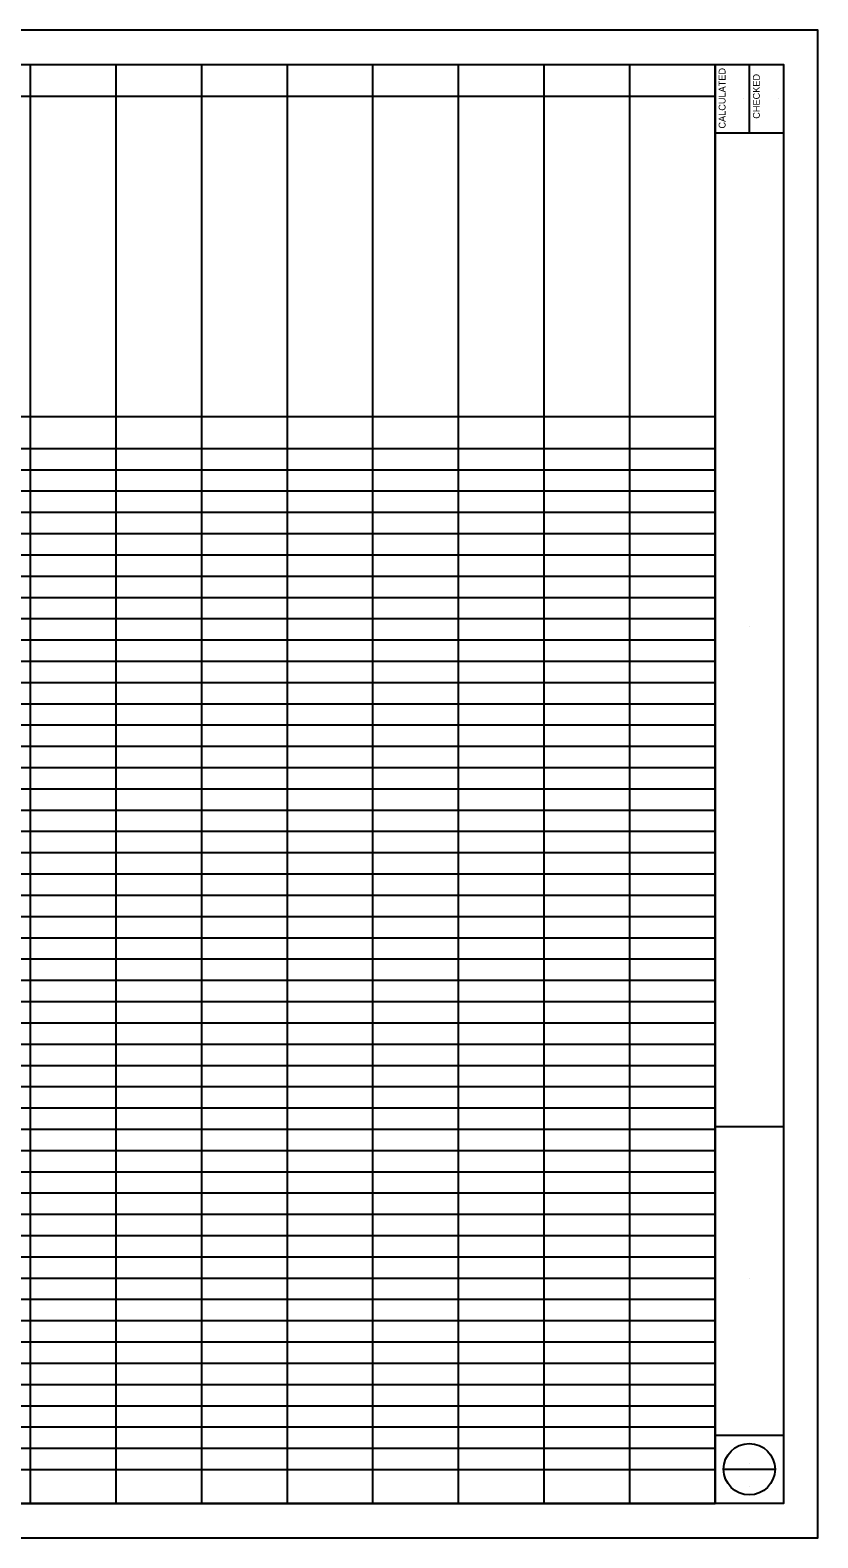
# Model space of a CAD drawing. Extents: x 10.3 to 44.3, y 3.4 to 25.4.
# Drawn here: x 32.81 to 44.31, y 3.4 to 25.4 of the extents above; entities that cross this region are included whole.
import ezdxf

# ---------------------------------------------------------------- set-up
doc = ezdxf.new("R2010")
doc.units = 0
for name, color, linetype in [('SH_Border', 7, 'Continuous'), ('SH_Cut_Line', 7, 'Continuous'), ('SH_Data', 7, 'Continuous'), ('SH_Text', 7, 'Continuous')]:
    doc.layers.add(name, color=color, linetype=linetype)

msp = doc.modelspace()

# ---------------------------------------------------------------- linework, layer by layer
at = {"layer": 'SH_Border'}
for p, q in [((42.806, 3.905), (42.806, 24.905)), ((43.306, 24.905), (43.306, 23.905)), ((42.806, 23.905), (43.806, 23.905)), ((42.806, 9.405), (43.806, 9.405)), ((42.806, 4.905), (43.806, 4.905))]:
    msp.add_line(p, q, dxfattribs=at)
msp.add_lwpolyline([(12.306, 24.905), (43.806, 24.905), (43.806, 3.905), (12.306, 3.905)], close=True, dxfattribs=at)
at = {"layer": 'SH_Cut_Line'}
msp.add_lwpolyline([(10.306, 3.405), (44.306, 3.405), (44.306, 25.405), (10.306, 25.405)], close=True, dxfattribs=at)
at = {"layer": 'SH_Data'}
for p, q in [((43.226, 24.408), (43.226, 24.408)), ((43.726, 24.408), (43.726, 24.408)), ((43.306, 16.696), (43.306, 16.696)), ((43.306, 7.196), (43.306, 7.196)), ((42.931, 4.405), (43.681, 4.405)), ((43.306, 4.49), (43.306, 4.49)), ((43.306, 4.15), (43.306, 4.15))]:
    msp.add_line(p, q, dxfattribs=at)
msp.add_circle((43.306, 4.405), 0.375, dxfattribs=at)
at = {"layer": 'SH_Text'}
for p, q in [((24.657, 24.905), (32.81, 24.905)), ((32.81, 24.905), (36.559, 24.905)), ((32.81, 24.905), (32.81, 19.767)), ((34.06, 24.905), (34.06, 19.767)), ((35.309, 24.905), (35.309, 19.767)), ((36.559, 24.905), (39.058, 24.905)), ((36.559, 24.905), (36.559, 19.767)), ((37.808, 24.905), (37.808, 19.767)), ((39.058, 24.905), (42.806, 24.905)), ((39.058, 24.905), (39.058, 19.767)), ((40.307, 24.905), (40.307, 19.767)), ((41.557, 24.905), (41.557, 19.767)), ((42.806, 24.905), (42.806, 19.767)), ((25.682, 24.439), (32.81, 24.439)), ((32.81, 24.439), (36.559, 24.439)), ((36.559, 24.439), (39.058, 24.439)), ((39.058, 24.439), (42.806, 24.439)), ((25.682, 19.767), (32.81, 19.767)), ((32.81, 19.767), (36.559, 19.767)), ((32.81, 19.767), (32.81, 11.851)), ((34.06, 19.767), (34.06, 11.851)), ((35.309, 19.767), (35.309, 11.851)), ((36.559, 19.767), (39.058, 19.767)), ((36.559, 19.767), (36.559, 11.851)), ((37.808, 19.767), (37.808, 11.851)), ((39.058, 19.767), (42.806, 19.767)), ((39.058, 19.767), (39.058, 11.851)), ((40.307, 19.767), (40.307, 11.851)), ((41.557, 19.767), (41.557, 11.851)), ((42.806, 19.767), (42.806, 11.851)), ((24.657, 19.301), (32.81, 19.301)), ((32.81, 19.301), (36.559, 19.301)), ((36.559, 19.301), (39.058, 19.301)), ((39.058, 19.301), (42.806, 19.301)), ((24.657, 18.991), (32.81, 18.991)), ((32.81, 18.991), (36.559, 18.991)), ((36.559, 18.991), (39.058, 18.991)), ((39.058, 18.991), (42.806, 18.991)), ((24.657, 18.681), (32.81, 18.681)), ((32.81, 18.681), (36.559, 18.681)), ((36.559, 18.681), (39.058, 18.681)), ((39.058, 18.681), (42.806, 18.681)), ((24.657, 18.37), (32.81, 18.37)), ((32.81, 18.37), (36.559, 18.37)), ((36.559, 18.37), (39.058, 18.37)), ((39.058, 18.37), (42.806, 18.37)), ((24.657, 18.06), (32.81, 18.06)), ((32.81, 18.06), (36.559, 18.06)), ((36.559, 18.06), (39.058, 18.06)), ((39.058, 18.06), (42.806, 18.06)), ((24.657, 17.749), (32.81, 17.749)), ((32.81, 17.749), (36.559, 17.749)), ((36.559, 17.749), (39.058, 17.749)), ((39.058, 17.749), (42.806, 17.749)), ((24.657, 17.439), (32.81, 17.439)), ((32.81, 17.439), (36.559, 17.439)), ((36.559, 17.439), (39.058, 17.439)), ((39.058, 17.439), (42.806, 17.439)), ((24.657, 17.128), (32.81, 17.128)), ((32.81, 17.128), (36.559, 17.128)), ((36.559, 17.128), (39.058, 17.128)), ((39.058, 17.128), (42.806, 17.128)), ((24.657, 16.818), (32.81, 16.818)), ((32.81, 16.818), (36.559, 16.818)), ((36.559, 16.818), (39.058, 16.818)), ((39.058, 16.818), (42.806, 16.818)), ((24.657, 16.508), (32.81, 16.508)), ((32.81, 16.508), (36.559, 16.508)), ((36.559, 16.508), (39.058, 16.508)), ((39.058, 16.508), (42.806, 16.508)), ((24.657, 16.197), (32.81, 16.197)), ((32.81, 16.197), (36.559, 16.197)), ((36.559, 16.197), (39.058, 16.197)), ((39.058, 16.197), (42.806, 16.197)), ((24.657, 15.887), (32.81, 15.887)), ((32.81, 15.887), (36.559, 15.887)), ((36.559, 15.887), (39.058, 15.887)), ((39.058, 15.887), (42.806, 15.887)), ((24.657, 15.576), (32.81, 15.576)), ((32.81, 15.576), (36.559, 15.576)), ((36.559, 15.576), (39.058, 15.576)), ((39.058, 15.576), (42.806, 15.576)), ((24.657, 15.266), (32.81, 15.266)), ((32.81, 15.266), (36.559, 15.266)), ((36.559, 15.266), (39.058, 15.266)), ((39.058, 15.266), (42.806, 15.266)), ((24.657, 14.956), (32.81, 14.956)), ((32.81, 14.956), (36.559, 14.956)), ((36.559, 14.956), (39.058, 14.956)), ((39.058, 14.956), (42.806, 14.956)), ((24.657, 14.645), (32.81, 14.645)), ((32.81, 14.645), (36.559, 14.645)), ((36.559, 14.645), (39.058, 14.645)), ((39.058, 14.645), (42.806, 14.645)), ((24.657, 14.335), (32.81, 14.335)), ((32.81, 14.335), (36.559, 14.335)), ((36.559, 14.335), (39.058, 14.335)), ((39.058, 14.335), (42.806, 14.335)), ((24.657, 14.024), (32.81, 14.024)), ((32.81, 14.024), (36.559, 14.024)), ((36.559, 14.024), (39.058, 14.024)), ((39.058, 14.024), (42.806, 14.024)), ((24.657, 13.714), (32.81, 13.714)), ((32.81, 13.714), (36.559, 13.714)), ((36.559, 13.714), (39.058, 13.714)), ((39.058, 13.714), (42.806, 13.714)), ((24.657, 13.403), (32.81, 13.403)), ((32.81, 13.403), (36.559, 13.403)), ((36.559, 13.403), (39.058, 13.403)), ((39.058, 13.403), (42.806, 13.403)), ((24.657, 13.093), (32.81, 13.093)), ((32.81, 13.093), (36.559, 13.093)), ((36.559, 13.093), (39.058, 13.093)), ((39.058, 13.093), (42.806, 13.093)), ((24.657, 12.783), (32.81, 12.783)), ((32.81, 12.783), (36.559, 12.783)), ((36.559, 12.783), (39.058, 12.783)), ((39.058, 12.783), (42.806, 12.783)), ((24.657, 12.472), (32.81, 12.472)), ((32.81, 12.472), (36.559, 12.472)), ((36.559, 12.472), (39.058, 12.472)), ((39.058, 12.472), (42.806, 12.472)), ((24.657, 12.162), (32.81, 12.162)), ((32.81, 12.162), (36.559, 12.162)), ((36.559, 12.162), (39.058, 12.162)), ((39.058, 12.162), (42.806, 12.162)), ((24.657, 11.851), (32.81, 11.851)), ((32.81, 11.851), (36.559, 11.851)), ((32.81, 11.851), (32.81, 3.905)), ((34.06, 11.851), (34.06, 3.905)), ((35.309, 11.851), (35.309, 3.905)), ((36.559, 11.851), (39.058, 11.851)), ((36.559, 11.851), (36.559, 3.905)), ((37.808, 11.851), (37.808, 3.905)), ((39.058, 11.851), (42.806, 11.851)), ((39.058, 11.851), (39.058, 3.905)), ((40.307, 11.851), (40.307, 3.905)), ((41.557, 11.851), (41.557, 3.905)), ((42.806, 11.851), (42.806, 3.905)), ((24.657, 11.541), (32.81, 11.541)), ((32.81, 11.541), (36.559, 11.541)), ((36.559, 11.541), (39.058, 11.541)), ((39.058, 11.541), (42.806, 11.541)), ((27.204, 11.23), (32.81, 11.23)), ((32.81, 11.23), (36.559, 11.23)), ((36.559, 11.23), (39.058, 11.23)), ((39.058, 11.23), (42.806, 11.23)), ((24.657, 10.92), (32.81, 10.92)), ((32.81, 10.92), (36.559, 10.92)), ((36.559, 10.92), (39.058, 10.92)), ((39.058, 10.92), (42.806, 10.92)), ((27.204, 10.61), (32.81, 10.61)), ((32.81, 10.61), (36.559, 10.61)), ((36.559, 10.61), (39.058, 10.61)), ((39.058, 10.61), (42.806, 10.61)), ((24.657, 10.299), (32.81, 10.299)), ((32.81, 10.299), (36.559, 10.299)), ((36.559, 10.299), (39.058, 10.299)), ((39.058, 10.299), (42.806, 10.299)), ((24.657, 9.989), (32.81, 9.989)), ((32.81, 9.989), (36.559, 9.989)), ((36.559, 9.989), (39.058, 9.989)), ((39.058, 9.989), (42.806, 9.989)), ((24.657, 9.678), (32.81, 9.678)), ((32.81, 9.678), (36.559, 9.678)), ((36.559, 9.678), (39.058, 9.678)), ((39.058, 9.678), (42.806, 9.678)), ((24.657, 9.368), (32.81, 9.368)), ((32.81, 9.368), (36.559, 9.368)), ((36.559, 9.368), (39.058, 9.368)), ((39.058, 9.368), (42.806, 9.368)), ((24.657, 9.058), (32.81, 9.058)), ((32.81, 9.058), (36.559, 9.058)), ((36.559, 9.058), (39.058, 9.058)), ((39.058, 9.058), (42.806, 9.058)), ((24.657, 8.747), (32.81, 8.747)), ((32.81, 8.747), (36.559, 8.747)), ((36.559, 8.747), (39.058, 8.747)), ((39.058, 8.747), (42.806, 8.747)), ((24.657, 8.437), (32.81, 8.437)), ((32.81, 8.437), (36.559, 8.437)), ((36.559, 8.437), (39.058, 8.437)), ((39.058, 8.437), (42.806, 8.437)), ((24.657, 8.126), (32.81, 8.126)), ((32.81, 8.126), (36.559, 8.126)), ((36.559, 8.126), (39.058, 8.126)), ((39.058, 8.126), (42.806, 8.126)), ((24.657, 7.816), (32.81, 7.816)), ((32.81, 7.816), (36.559, 7.816)), ((36.559, 7.816), (39.058, 7.816)), ((39.058, 7.816), (42.806, 7.816)), ((24.657, 7.505), (32.81, 7.505)), ((32.81, 7.505), (36.559, 7.505)), ((36.559, 7.505), (39.058, 7.505)), ((39.058, 7.505), (42.806, 7.505)), ((24.657, 7.195), (32.81, 7.195)), ((32.81, 7.195), (36.559, 7.195)), ((36.559, 7.195), (39.058, 7.195)), ((39.058, 7.195), (42.806, 7.195)), ((24.657, 6.885), (32.81, 6.885)), ((32.81, 6.885), (36.559, 6.885)), ((36.559, 6.885), (39.058, 6.885)), ((39.058, 6.885), (42.806, 6.885)), ((24.657, 6.574), (32.81, 6.574)), ((32.81, 6.574), (36.559, 6.574)), ((36.559, 6.574), (39.058, 6.574)), ((39.058, 6.574), (42.806, 6.574)), ((24.657, 6.264), (32.81, 6.264)), ((32.81, 6.264), (36.559, 6.264)), ((36.559, 6.264), (39.058, 6.264)), ((39.058, 6.264), (42.806, 6.264)), ((24.657, 5.953), (32.81, 5.953)), ((32.81, 5.953), (36.559, 5.953)), ((36.559, 5.953), (39.058, 5.953)), ((39.058, 5.953), (42.806, 5.953)), ((24.657, 5.643), (32.81, 5.643)), ((32.81, 5.643), (36.559, 5.643)), ((36.559, 5.643), (39.058, 5.643)), ((39.058, 5.643), (42.806, 5.643)), ((24.657, 5.332), (32.81, 5.332)), ((32.81, 5.332), (36.559, 5.332)), ((36.559, 5.332), (39.058, 5.332)), ((39.058, 5.332), (42.806, 5.332)), ((24.657, 5.022), (32.81, 5.022)), ((32.81, 5.022), (36.559, 5.022)), ((36.559, 5.022), (39.058, 5.022)), ((39.058, 5.022), (42.806, 5.022)), ((24.657, 4.712), (32.81, 4.712)), ((32.81, 4.712), (36.559, 4.712)), ((36.559, 4.712), (39.058, 4.712)), ((39.058, 4.712), (42.806, 4.712)), ((24.657, 4.401), (32.81, 4.401)), ((32.81, 4.401), (36.559, 4.401)), ((36.559, 4.401), (39.058, 4.401)), ((39.058, 4.401), (42.806, 4.401)), ((24.657, 3.905), (32.81, 3.905)), ((32.81, 3.905), (36.559, 3.905)), ((36.559, 3.905), (39.058, 3.905)), ((39.058, 3.905), (42.806, 3.905))]:
    msp.add_line(p, q, dxfattribs=at)

# ---------------------------------------------------------------- texts
at = {"layer": 'SH_Data'}
for s, p in [('CALCULATED', (42.959, 23.969)), ('CHECKED', (43.459, 24.112))]:
    msp.add_text(s, height=0.1, rotation=90, dxfattribs=at).set_placement(p)

doc.saveas('drawing.dxf')
